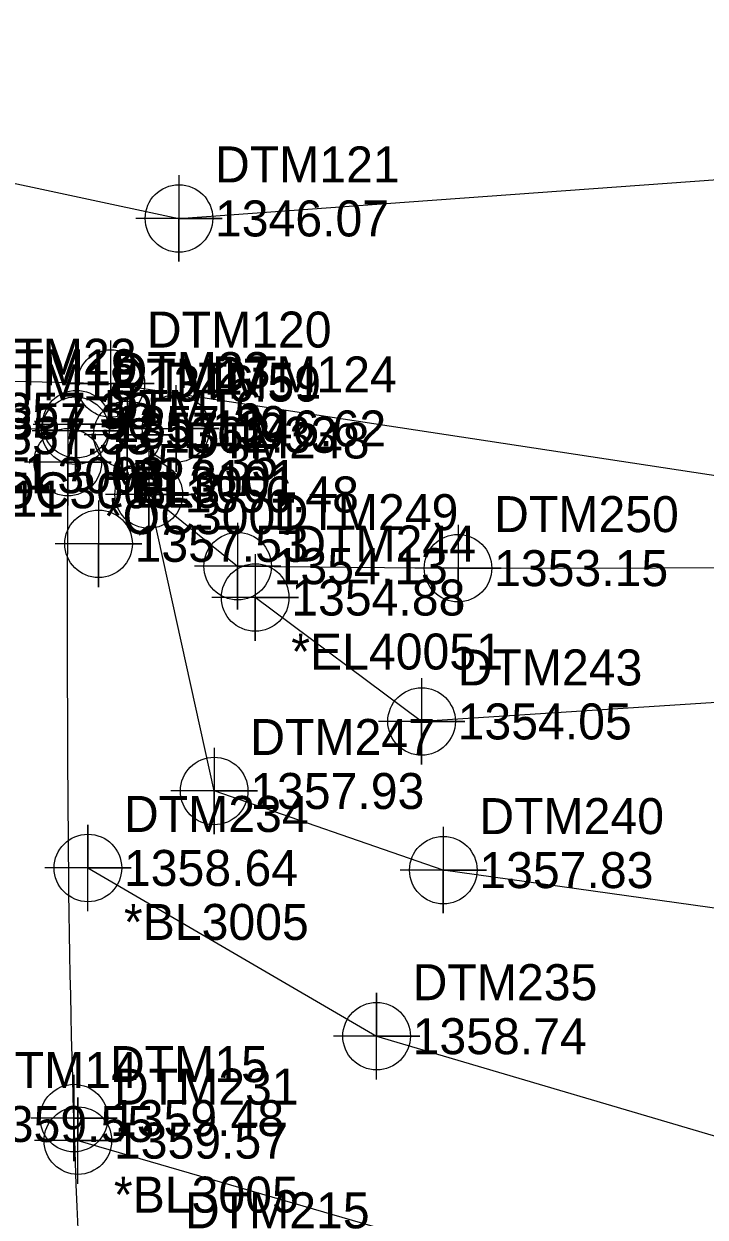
# Model space of a CAD drawing. Extents: x 1251905 to 1252853, y 859795 to 860170.
# Drawn here: x 1252040.3 to 1252087.6, y 859945.7 to 860028.5 of the extents above; entities that cross this region are included whole.
import ezdxf

# ---------------------------------------------------------------- set-up
doc = ezdxf.new("R2010")
doc.units = 0
for name, color, linetype in [('Default Symbol CELL', 7, 'Continuous'), ('Default Symbol Cogo Elevation', 7, 'Continuous'), ('Default Symbol Cogo Number', 7, 'Continuous'), ('Exist DTM Breakline', 7, 'Continuous'), ('Exist DTM Breakline Cogo Comment', 7, 'Continuous'), ('Exist DTM Breakline Cogo Elevation', 7, 'Continuous'), ('Exist DTM Breakline Cogo Number', 7, 'Continuous'), ('Exist DTM Breakline Cogo Point CELL', 7, 'Continuous'), ('Exist DTM Breakline Underwater', 7, 'Continuous'), ('Exist DTM Breakline Underwater Cogo Elevation', 7, 'Continuous'), ('Exist DTM Breakline Underwater Cogo Number', 7, 'Continuous'), ('Exist DTM Breakline Underwater Cogo Point CELL', 7, 'Continuous'), ('Exist DTM Crownline', 7, 'Continuous'), ('Exist DTM Crownline Cogo Comment', 7, 'Continuous'), ('Exist DTM Crownline Cogo Elevation', 7, 'Continuous'), ('Exist DTM Crownline Cogo Number', 7, 'Continuous'), ('Exist DTM Regular Point Cogo Elevation', 7, 'Continuous'), ('Exist DTM Regular Point Cogo Number', 7, 'Continuous'), ('Exist Hydro Stream or Body of Water', 7, 'Continuous'), ('Exist Hydro Stream or Body of Water Cogo Elevation', 7, 'Continuous'), ('Exist Hydro Stream or Body of Water Cogo Number', 7, 'Continuous'), ('Exist Hydro Stream or Body of Water Cogo Point CELL', 7, 'Continuous'), ('Exist Roads EOP', 7, 'Continuous'), ('Exist Roads EOP Cogo Comment', 7, 'Continuous'), ('Exist Roads EOP Cogo Elevation', 7, 'Continuous'), ('Exist Roads EOP Cogo Number', 7, 'Continuous'), ('Exist Roads EOP Cogo Point CELL', 7, 'Continuous'), ('Exist Roads Soil', 7, 'Continuous'), ('Exist Roads Soil Cogo Comment', 7, 'Continuous'), ('Exist Roads Soil Cogo Elevation', 7, 'Continuous'), ('Exist Roads Soil Cogo Number', 7, 'Continuous'), ('Exist Roads Soil Cogo Point CELL', 7, 'Continuous'), ('Exist Structure Major Deck Tunnel Box Culvert Cogo Comment', 7, 'Continuous'), ('Exist Structure Major Deck Tunnel Box Culvert Cogo Elevation', 7, 'Continuous'), ('Exist Structure Major Deck Tunnel Box Culvert Cogo Number', 7, 'Continuous'), ('Exist Structure Major Deck Tunnel Box Culvert Cogo Point CELL', 7, 'Continuous')]:
    doc.layers.add(name, color=color, linetype=linetype)

msp = doc.modelspace()

# ---------------------------------------------------------------- linework, layer by layer
at = {"layer": 'Default Symbol CELL'}
msp.add_lwpolyline([(1252045.53, 859995.411), (1252045.53, 859989.411), (1252045.53, 859992.411), (1252048.53, 859992.411), (1252042.53, 859992.411)], dxfattribs=at)
msp.add_circle((1252045.53, 859992.411), 2.344, dxfattribs=at)
at = {"layer": 'Exist DTM Breakline'}
for points in [[(1252142.933, 859962.19), (1252113.232, 859963.613), (1252069.451, 859969.754), (1252053.554, 859975.248), (1252049.013, 859995.838), (1252055.18, 859990.86), (1252070.476, 859990.723), (1252097.889, 859990.776), (1252129.235, 859993.878), (1252158.893, 860000.874), (1252188.538, 859999.284), (1252205.671, 859994.157)], [(1252144.878, 859971.595), (1252098.791, 859982.055), (1252067.947, 859980.078), (1252056.401, 859988.682)]]:
    msp.add_lwpolyline(points, dxfattribs=at)
at = {"layer": 'Exist DTM Breakline Cogo Point CELL'}
for points in [[(1252049.013, 859998.838), (1252049.013, 859992.838), (1252049.013, 859995.838), (1252052.013, 859995.838), (1252046.013, 859995.838)], [(1252055.18, 859993.86), (1252055.18, 859987.86), (1252055.18, 859990.86), (1252058.18, 859990.86), (1252052.18, 859990.86)], [(1252070.476, 859993.723), (1252070.476, 859987.723), (1252070.476, 859990.723), (1252073.476, 859990.723), (1252067.476, 859990.723)], [(1252056.401, 859991.682), (1252056.401, 859985.682), (1252056.401, 859988.682), (1252059.401, 859988.682), (1252053.401, 859988.682)], [(1252067.947, 859983.078), (1252067.947, 859977.078), (1252067.947, 859980.078), (1252070.947, 859980.078), (1252064.947, 859980.078)], [(1252053.554, 859978.248), (1252053.554, 859972.248), (1252053.554, 859975.248), (1252056.554, 859975.248), (1252050.554, 859975.248)], [(1252069.451, 859972.754), (1252069.451, 859966.754), (1252069.451, 859969.754), (1252072.451, 859969.754), (1252066.451, 859969.754)]]:
    msp.add_lwpolyline(points, dxfattribs=at)
for centre in [(1252049.013, 859995.838), (1252055.18, 859990.86), (1252070.476, 859990.723), (1252056.401, 859988.682), (1252067.947, 859980.078), (1252053.554, 859975.248), (1252069.451, 859969.754)]:
    msp.add_circle(centre, 2.344, dxfattribs=at)
at = {"layer": 'Exist DTM Breakline Underwater'}
msp.add_lwpolyline([(1251927.42, 860049.663), (1251960.607, 860043.428), (1251991.544, 860038.543), (1252023.095, 860021.002), (1252051.108, 860015.006), (1252097.444, 860018.35), (1252136.124, 860025.415), (1252179.795, 860024.836), (1252209.042, 860015.729)], dxfattribs=at)
at = {"layer": 'Exist DTM Breakline Underwater Cogo Point CELL'}
msp.add_lwpolyline([(1252051.108, 860018.006), (1252051.108, 860012.006), (1252051.108, 860015.006), (1252054.108, 860015.006), (1252048.108, 860015.006)], dxfattribs=at)
msp.add_circle((1252051.108, 860015.006), 2.344, dxfattribs=at)
at = {"layer": 'Exist DTM Crownline'}
msp.add_spline([(1252046.752, 859804.377), (1252041.79, 859852.778), (1252037.509, 859902.564), (1252034.798, 859952.124), (1252034.696, 859999.877)], degree=3, dxfattribs=at)
at = {"layer": 'Exist Hydro Stream or Body of Water'}
msp.add_lwpolyline([(1251923.519, 860032.492), (1251957.999, 860032.964), (1251987.699, 860026.743), (1252004.412, 860018.883), (1252004.612, 860014.582), (1251994.716, 860013.049), (1252010.915, 860007.676), (1252019.462, 860003.97), (1252019.665, 860004.195), (1252046.38, 860003.539), (1252090.782, 859996.797), (1252140.715, 860010.791), (1252179.759, 860006.581), (1252205.549, 860000.12)], dxfattribs=at)
at = {"layer": 'Exist Hydro Stream or Body of Water Cogo Point CELL'}
for points in [[(1252043.38, 860003.539), (1252049.38, 860003.539), (1252046.38, 860003.539), (1252046.38, 860000.539), (1252046.38, 860006.539)], [(1252047.908, 860000.42), (1252053.908, 860000.42), (1252050.908, 860000.42), (1252050.908, 859997.42), (1252050.908, 860003.42)]]:
    msp.add_lwpolyline(points, dxfattribs=at)
for centre in [(1252046.38, 860003.539), (1252050.908, 860000.42)]:
    msp.add_circle(centre, 2.344, dxfattribs=at)
at = {"layer": 'Exist Roads EOP'}
msp.add_line((1252043.399, 859998.083), (1252043.922, 860000.266), dxfattribs=at)
msp.add_lwpolyline([(1252025.059, 860001.178), (1252043.922, 860000.266)], dxfattribs=at)
msp.add_spline([(1252056.897, 859804.944), (1252051.57, 859853.552), (1252046.862, 859903.357), (1252043.821, 859952.535), (1252043.399, 859998.083)], degree=3, dxfattribs=at)
at = {"layer": 'Exist Roads EOP Cogo Point CELL'}
for points in [[(1252043.922, 860003.266), (1252043.922, 859997.266), (1252043.922, 860000.266), (1252046.922, 860000.266), (1252040.922, 860000.266)], [(1252047.525, 860002.984), (1252047.525, 859996.984), (1252047.525, 859999.984), (1252050.525, 859999.984), (1252044.525, 859999.984)], [(1252043.399, 860001.083), (1252043.399, 859995.083), (1252043.399, 859998.083), (1252046.399, 859998.083), (1252040.399, 859998.083)], [(1252043.821, 859955.535), (1252043.821, 859949.535), (1252043.821, 859952.535), (1252046.821, 859952.535), (1252040.821, 859952.535)]]:
    msp.add_lwpolyline(points, dxfattribs=at)
for centre in [(1252043.922, 860000.266), (1252047.525, 859999.984), (1252043.399, 859998.083), (1252043.821, 859952.535)]:
    msp.add_circle(centre, 2.344, dxfattribs=at)
at = {"layer": 'Exist Roads Soil'}
for points in [[(1252044.791, 859969.904), (1252064.824, 859958.222), (1252092.402, 859950.074), (1252137.619, 859940.278)], [(1252044.096, 859950.97), (1252090.774, 859937.412), (1252136.088, 859930.761)]]:
    msp.add_lwpolyline(points, dxfattribs=at)
at = {"layer": 'Exist Roads Soil Cogo Point CELL'}
for points in [[(1252044.791, 859966.904), (1252044.791, 859972.904), (1252044.791, 859969.904), (1252047.791, 859969.904), (1252041.791, 859969.904)], [(1252064.824, 859955.222), (1252064.824, 859961.222), (1252064.824, 859958.222), (1252067.824, 859958.222), (1252061.824, 859958.222)], [(1252044.096, 859947.97), (1252044.096, 859953.97), (1252044.096, 859950.97), (1252047.096, 859950.97), (1252041.096, 859950.97)]]:
    msp.add_lwpolyline(points, dxfattribs=at)
for centre in [(1252044.791, 859969.904), (1252064.824, 859958.222), (1252044.096, 859950.97)]:
    msp.add_circle(centre, 2.344, dxfattribs=at)
at = {"layer": 'Exist Structure Major Deck Tunnel Box Culvert Cogo Point CELL'}
msp.add_lwpolyline([(1252040.997, 860000.725), (1252046.997, 860000.725), (1252043.997, 860000.725), (1252043.997, 860003.725), (1252043.997, 859997.725)], dxfattribs=at)
msp.add_circle((1252043.997, 860000.725), 2.344, dxfattribs=at)

# ---------------------------------------------------------------- texts
at = {"layer": 'Default Symbol Cogo Elevation'}
msp.add_text('1357.53', height=2.5, dxfattribs=at).set_placement((1252048.03, 859991.161))
at = {"layer": 'Default Symbol Cogo Number'}
msp.add_text('BL3', height=2.5, dxfattribs=at).set_placement((1252048.03, 859994.911))
at = {"layer": 'Exist DTM Breakline Cogo Comment'}
msp.add_text('*EL40051', height=2.5, dxfattribs=at).set_placement((1252058.901, 859983.682))
at = {"layer": 'Exist DTM Breakline Cogo Elevation'}
for s, p in [('1356.48', (1252051.513, 859994.588)), ('1354.13', (1252057.68, 859989.61)), ('1353.15', (1252072.976, 859989.473)), ('1354.88', (1252058.901, 859987.432)), ('1354.05', (1252070.447, 859978.828)), ('1357.93', (1252056.054, 859973.998)), ('1357.83', (1252071.951, 859968.504))]:
    msp.add_text(s, height=2.5, dxfattribs=at).set_placement(p)
at = {"layer": 'Exist DTM Breakline Cogo Number'}
for s, p in [('DTM248', (1252051.513, 859998.338)), ('DTM249', (1252057.68, 859993.36)), ('DTM250', (1252072.976, 859993.223)), ('DTM244', (1252058.901, 859991.182)), ('DTM243', (1252070.447, 859982.578)), ('DTM247', (1252056.054, 859977.748)), ('DTM240', (1252071.951, 859972.254)), ('DTM215', (1252051.522, 859944.88))]:
    msp.add_text(s, height=2.5, dxfattribs=at).set_placement(p)
at = {"layer": 'Exist DTM Breakline Underwater Cogo Elevation'}
msp.add_text('1346.07', height=2.5, dxfattribs=at).set_placement((1252053.608, 860013.756))
at = {"layer": 'Exist DTM Breakline Underwater Cogo Number'}
msp.add_text('DTM121', height=2.5, dxfattribs=at).set_placement((1252053.608, 860017.506))
at = {"layer": 'Exist DTM Crownline Cogo Comment'}
for s, p in [('*EL3008', (1252037.285, 859995.924)), ('*OC3008', (1252037.196, 859994.877))]:
    msp.add_text(s, height=2.5, dxfattribs=at).set_placement(p)
at = {"layer": 'Exist DTM Crownline Cogo Elevation'}
for s, p in [('1357.30', (1252037.285, 859999.674)), ('1357.33', (1252037.196, 859998.627)), ('1359.55', (1252037.298, 859950.874))]:
    msp.add_text(s, height=2.5, dxfattribs=at).set_placement(p)
at = {"layer": 'Exist DTM Crownline Cogo Number'}
for s, p in [('DTM19', (1252037.285, 860003.424)), ('DTM18', (1252037.196, 860002.377)), ('DTM14', (1252037.298, 859954.624))]:
    msp.add_text(s, height=2.5, dxfattribs=at).set_placement(p)
at = {"layer": 'Exist DTM Regular Point Cogo Elevation'}
msp.add_text('1357.30', height=2.5, dxfattribs=at).set_placement((1252037.208, 860000.401))
at = {"layer": 'Exist DTM Regular Point Cogo Number'}
msp.add_text('DTM22', height=2.5, dxfattribs=at).set_placement((1252037.208, 860004.151))
at = {"layer": 'Exist Hydro Stream or Body of Water Cogo Elevation'}
for s, p in [('1346.59', (1252048.88, 860002.289)), ('1346.62', (1252053.408, 859999.17))]:
    msp.add_text(s, height=2.5, dxfattribs=at).set_placement(p)
at = {"layer": 'Exist Hydro Stream or Body of Water Cogo Number'}
for s, p in [('DTM120', (1252048.88, 860006.039)), ('DTM124', (1252053.408, 860002.92))]:
    msp.add_text(s, height=2.5, dxfattribs=at).set_placement(p)
at = {"layer": 'Exist Roads EOP Cogo Comment'}
for s, p in [('*EL30011', (1252027.559, 859996.178)), ('*EL3001', (1252046.422, 859995.266)), ('*OC30011', (1252027.519, 859994.306)), ('*OC3001', (1252045.899, 859993.083))]:
    msp.add_text(s, height=2.5, dxfattribs=at).set_placement(p)
at = {"layer": 'Exist Roads EOP Cogo Elevation'}
for s, p in [('1357.19', (1252046.422, 859999.016)), ('1362.33', (1252050.025, 859998.734)), ('1357.35', (1252045.899, 859996.833)), ('1359.48', (1252046.321, 859951.285))]:
    msp.add_text(s, height=2.5, dxfattribs=at).set_placement(p)
at = {"layer": 'Exist Roads EOP Cogo Number'}
for s, p in [('DTM17', (1252046.422, 860002.766)), ('DTM51', (1252050.025, 860002.484)), ('DTM16', (1252045.899, 860000.583)), ('DTM15', (1252046.321, 859955.035))]:
    msp.add_text(s, height=2.5, dxfattribs=at).set_placement(p)
at = {"layer": 'Exist Roads Soil Cogo Comment'}
for p in [(1252047.291, 859964.904), (1252046.596, 859945.97)]:
    msp.add_text('*BL3005', height=2.5, dxfattribs=at).set_placement(p)
at = {"layer": 'Exist Roads Soil Cogo Elevation'}
for s, p in [('1358.64', (1252047.291, 859968.654)), ('1358.74', (1252067.324, 859956.972)), ('1359.57', (1252046.596, 859949.72))]:
    msp.add_text(s, height=2.5, dxfattribs=at).set_placement(p)
at = {"layer": 'Exist Roads Soil Cogo Number'}
for s, p in [('DTM234', (1252047.291, 859972.404)), ('DTM235', (1252067.324, 859960.722)), ('DTM231', (1252046.596, 859953.47))]:
    msp.add_text(s, height=2.5, dxfattribs=at).set_placement(p)
at = {"layer": 'Exist Structure Major Deck Tunnel Box Culvert Cogo Comment'}
msp.add_text('*BL3101', height=2.5, dxfattribs=at).set_placement((1252046.497, 859995.725))
at = {"layer": 'Exist Structure Major Deck Tunnel Box Culvert Cogo Elevation'}
msp.add_text('1357.30', height=2.5, dxfattribs=at).set_placement((1252046.497, 859999.475))
at = {"layer": 'Exist Structure Major Deck Tunnel Box Culvert Cogo Number'}
msp.add_text('DTM23', height=2.5, dxfattribs=at).set_placement((1252046.497, 860003.225))

doc.saveas('drawing.dxf')
